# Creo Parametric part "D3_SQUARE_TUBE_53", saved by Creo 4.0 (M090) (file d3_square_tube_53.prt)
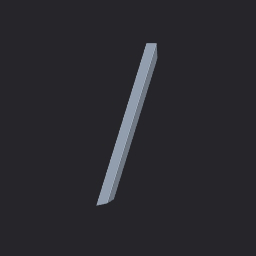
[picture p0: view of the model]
Units: Custom; MM, KILOGRAM, SECS
Materials in the file: STEEL

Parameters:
  BUW_NAME = "SQUARE TUBE"
  BUW_TYPE = "DIN EN 10210"
  BUW_SIZE = "60x60x3.0"
  BUW_LENGTH_STR = "1075.3"
  PTC_MATERIAL_NAME = "STEEL"
  BUW_PROFIL_TYPE = "square_tube"
  BUW_PROFILE_PATH = "parts/profiles/steel_beams_mm/"
  BUW_PROFILE_NAME_LANG = "SQUARE TUBE"
  BUW_TAB_SEL_INFO = "2  0 2  3 19"
  MITRE_SYM_X_S = "/"
  MITRE_SYM_X_E = "\"
  MITRE_SYM_X = "/---\"
  MITRE_BOM_X = "X /---\"
  MITRE_SYM_Y_S = "|"
  MITRE_SYM_Y_E = "\"
  MITRE_SYM_Y = "|---\"
  MITRE_BOM_Y = "Y |---\"
  BUW_DOUBLE_TO_STR_INFO = "X_ROT_S2 2 X_ROT_E2 2 Y_ROT_S2 2 Y_ROT_E2 2"
  X_ROT_S2_STR = "45"
  X_ROT_E2_STR = "39"
  Y_ROT_S2_STR = "90"
  Y_ROT_E2_STR = "75"
  BOM_ANGLE_S = "X 45°"
  BOM_ANGLE_E = "SPECIAL"
  EFX_ITEM_NR = "6"
  PROFIL_RASTER_POS = "X_0"
  BUW_OBJECT_ROLE = "PROFIL_SYSTEM_BORE_END_POINTS"
  PRO_UNIT_SYS = "Custom"

Other parameters: BUW_LENGTH, X_ROT_S2, X_ROT_E2, Y_ROT_S2, Y_ROT_E2, D8, D93, D94, d26, d8, d93, d94, d98, D98, D0, D4, D1, D5, SHEAR_MODULUS, THERM_EXPANSION_REF_TEMPERATURE, STRUCTURAL_DAMPING_COEFFICIENT, STRESS_LIMIT_FOR_TENSION, STRESS_LIMIT_FOR_COMPRESSION, STRESS_LIMIT_FOR_SHEAR, EMISSIVITY

Created from: SQUARE_TUBE.PRT

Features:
  1. datum plane "YZ"
  2. datum plane "XZ"
  3. datum plane "XY"
  4. coordinate system
  5. coordinate system
  6. coordinate system
  7. coordinate system
  8. datum plane "DTM3"
  9. datum plane "DTM4"
  10. datum plane "DTM5"
  11. protrusion
  12. round
  13. round
  14. datum axis
  15. datum point "PNT0"
  16. datum point

Other named items: PROFIL_CUT_QUILT, PROFILE_LENGTH_DIM, CONTACT_SURF_3, CONTACT_SURF_2, CONTACT_SURF_1, CONTACT_SURF_0, E, START_SURFACE, END_SURFACE, SIDE_SURF_3, SIDE_SURF_0, SIDE_SURF_1, SIDE_SURF_2, EDGE_7_S, EDGE_7_E, EDGE_1_S, EDGE_1_E, EDGE_3_S, EDGE_3_E, EDGE_5_S, EDGE_5_E, EDGE_6_S, EDGE_4_S, EDGE_2_S, EDGE_0_S, EDGE_6_E, EDGE_4_E, EDGE_2_E, EDGE_0_E, CS0, CS_S, CS_E, CS3

Named dimensions: X_ROT_S, Y_ROT_S, Z_OFF_S, X_ROT_E, Y_ROT_E, Z_OFF_E, PC_L, BUW_LENGTH_Z_MIN, BUW_LENGTH_DIM

Layers: 00_PROFIL_DATUM, 00_PROFIL_DRW_HIDE, 00_PROFIL_END_CSYS, 00_PROFIL_GEOMETRY, 00_PROFIL_QUILT, 00_PROFIL_SIZE_NOTE

Surfaces: 10 plane, 8 cylinder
